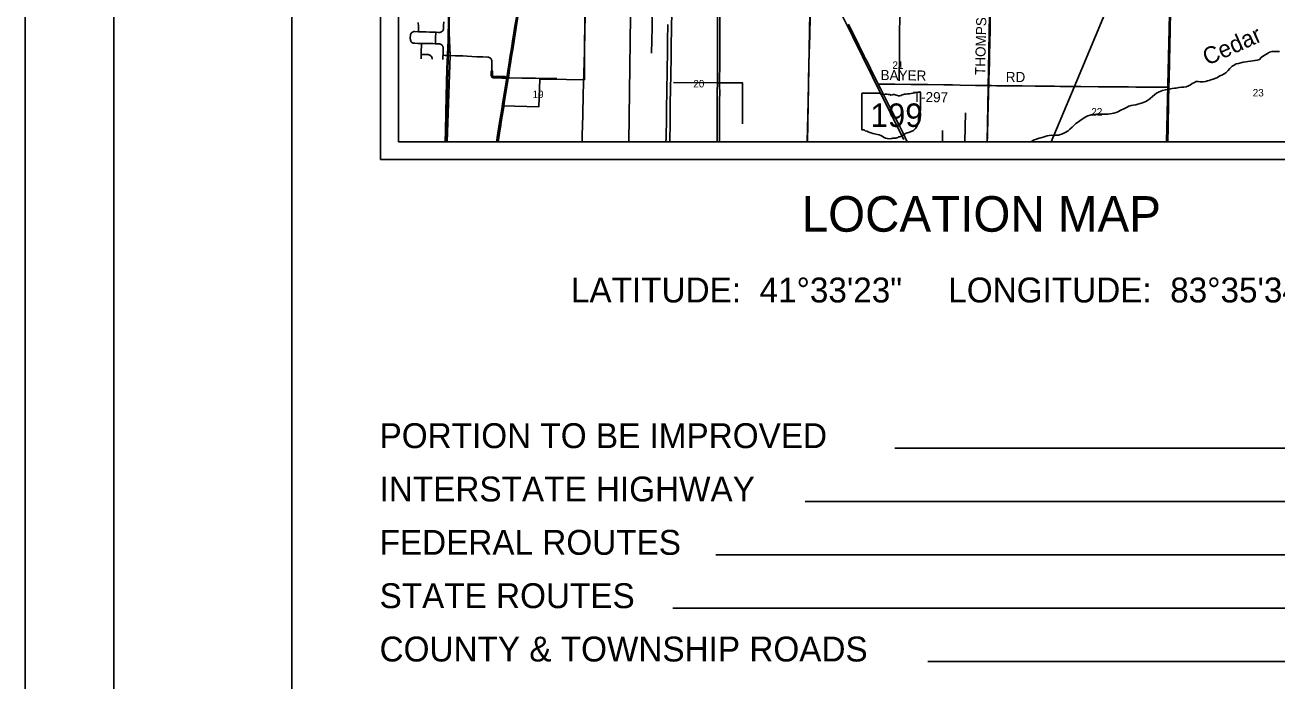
# Model space of a CAD drawing. Extents: x 0 to 34, y 0 to 22.
# Drawn here: x 0 to 7.04, y 11.07 to 14.76 of the extents above; entities that cross this region are included whole.
import ezdxf

# ---------------------------------------------------------------- set-up
doc = ezdxf.new("R2010")
doc.units = 0
for name, color, linetype in [('GM_X_City_Street', 7, 'Continuous'), ('GM_X_Corporation', 7, 'Continuous'), ('GM_X_County_Road', 7, 'Continuous'), ('GM_X_Interstate_Route', 7, 'Continuous'), ('GM_X_Minor_River', 7, 'Continuous'), ('GM_X_Minor_River_Text', 7, 'Continuous'), ('GM_X_Rail_Line', 7, 'Continuous'), ('GM_X_Section_Text', 7, 'Continuous'), ('GM_X_State_Location', 7, 'Continuous'), ('GM_X_State_Route', 7, 'Continuous'), ('GM_X_State_Shield', 7, 'Continuous'), ('GM_X_Township_Road', 7, 'Continuous'), ('GM_X_Township_Road_Text', 7, 'Continuous'), ('SH_Border', 7, 'Continuous'), ('SH_Cut_Line', 7, 'Continuous'), ('SH_Data', 7, 'Continuous'), ('SH_Text', 7, 'Continuous')]:
    doc.layers.add(name, color=color, linetype=linetype)

msp = doc.modelspace()

# ---------------------------------------------------------------- linework, layer by layer
at = {"layer": 'GM_X_City_Street'}
msp.add_line((2.71, 14.4594), (2.7187, 14.4592), dxfattribs=at)
for points in [[(2.3508, 14.5624), (2.3512, 14.5805), (2.3513, 14.586), (2.3513, 14.5954), (2.3519, 14.6215), (2.3519, 14.6284), (2.3515, 14.6316), (2.3509, 14.6341), (2.3499, 14.6366), (2.3482, 14.6394), (2.3463, 14.6419), (2.344, 14.6442), (2.3415, 14.6462), (2.3387, 14.6478), (2.3356, 14.649), (2.3325, 14.6498), (2.3287, 14.6502), (2.3212, 14.6504), (2.3085, 14.6509), (2.3075, 14.6509), (2.2939, 14.6515), (2.2634, 14.6523), (2.2305, 14.6531), (2.2294, 14.6531), (2.2099, 14.6532), (2.1932, 14.6533), (2.1883, 14.6535), (2.1854, 14.6541), (2.1825, 14.655), (2.1793, 14.6566), (2.1768, 14.6582), (2.1745, 14.6602), (2.1725, 14.6624), (2.1709, 14.6649), (2.1695, 14.6675), (2.1683, 14.6709), (2.1676, 14.6745), (2.1673, 14.6781), (2.1673, 14.6861), (2.1677, 14.6972), (2.1681, 14.7008), (2.1689, 14.7037), (2.17, 14.7065), (2.1715, 14.709), (2.1734, 14.7114), (2.1755, 14.7135), (2.1778, 14.7154), (2.1804, 14.7169), (2.1831, 14.7181), (2.186, 14.7189), (2.1889, 14.7194), (2.1926, 14.7196), (2.2131, 14.7187), (2.2192, 14.7185), (2.2571, 14.7171), (2.2758, 14.7165), (2.3103, 14.7153), (2.3124, 14.7152), (2.3255, 14.7146), (2.3318, 14.7145), (2.3343, 14.7147), (2.3369, 14.7153), (2.3399, 14.7164), (2.3428, 14.7179), (2.3449, 14.7193), (2.3474, 14.7215), (2.3495, 14.7239), (2.3513, 14.7266), (2.3527, 14.7295), (2.3538, 14.7325), (2.3544, 14.7357), (2.3548, 14.7401), (2.3548, 14.7532), (2.3551, 14.7749)], [(2.2131, 14.7187), (2.2131, 14.7245), (2.2128, 14.7475), (2.2125, 14.7712)], [(2.2286, 14.5668), (2.2288, 14.573), (2.2291, 14.5908), (2.2293, 14.6046), (2.2294, 14.6442), (2.2294, 14.6531)], [(2.3085, 14.6509), (2.3089, 14.6599), (2.3091, 14.669), (2.3095, 14.6864), (2.3102, 14.7115), (2.3103, 14.7153)], [(2.2291, 14.5908), (2.2316, 14.5907), (2.2364, 14.5906), (2.246, 14.5904), (2.2621, 14.59), (2.2671, 14.5897), (2.2709, 14.5891), (2.274, 14.5883), (2.2769, 14.587), (2.2797, 14.5854), (2.2823, 14.5834), (2.2845, 14.5811), (2.2864, 14.5785), (2.288, 14.5757), (2.2891, 14.5727), (2.2898, 14.5695), (2.29, 14.5663), (2.29, 14.565)], [(2.3513, 14.586), (2.3628, 14.5854), (2.3919, 14.5845), (2.4213, 14.5837), (2.4499, 14.5834), (2.4624, 14.5828), (2.4863, 14.5816), (2.5126, 14.5791), (2.5424, 14.5779), (2.5747, 14.5772), (2.6034, 14.5761), (2.6078, 14.5754), (2.6115, 14.5742), (2.615, 14.5724), (2.618, 14.5699), (2.6206, 14.567), (2.6231, 14.5633), (2.6247, 14.5598), (2.6257, 14.5561), (2.6263, 14.551), (2.6264, 14.541), (2.6258, 14.5105), (2.6256, 14.5014)], [(2.6256, 14.5014), (2.6246, 14.5002), (2.6238, 14.4985), (2.6233, 14.4971), (2.6228, 14.495), (2.6223, 14.4882), (2.6221, 14.4764), (2.6225, 14.472), (2.6233, 14.469), (2.6247, 14.4662), (2.6265, 14.4638), (2.6286, 14.462), (2.6309, 14.4606)], [(2.6256, 14.5014), (2.6266, 14.5005), (2.6275, 14.4995), (2.6279, 14.4986), (2.6283, 14.4976), (2.6288, 14.4958), (2.629, 14.4939), (2.6291, 14.4908), (2.6291, 14.4815), (2.6292, 14.4778), (2.6297, 14.4746), (2.6301, 14.4728), (2.631, 14.4706), (2.6317, 14.4691), (2.6325, 14.4683), (2.6336, 14.4675)], [(2.6309, 14.4606), (2.6324, 14.4599), (2.6349, 14.4591), (2.6376, 14.4588), (2.6417, 14.4588), (2.6813, 14.4581), (2.7013, 14.4579), (2.7046, 14.4581), (2.7078, 14.4586), (2.71, 14.4594)], [(2.6336, 14.4675), (2.6356, 14.4673), (2.6395, 14.467), (2.6688, 14.4667), (2.6981, 14.4662), (2.7002, 14.4659), (2.7024, 14.4653), (2.7042, 14.4647), (2.7063, 14.4633), (2.7084, 14.4615), (2.71, 14.4594)], [(2.7187, 14.4592), (2.7264, 14.459), (2.794, 14.4572), (2.8374, 14.4568), (2.8715, 14.4565), (2.9056, 14.4561), (2.9335, 14.4557), (2.9646, 14.4551), (2.9925, 14.4549)]]:
    msp.add_lwpolyline(points, dxfattribs=at)
at = {"layer": 'GM_X_Corporation'}
for points in [[(2.1, 17.3213), (2.1, 14.1), (8.9, 14.1)], [(2.1, 17.3213), (2.1, 14.1), (2.6563, 14.1), (2.6875, 14.3022), (2.891, 14.2967), (2.8954, 14.4513), (3.0457, 14.4499), (3.1471, 14.4488), (3.1471, 14.4499), (3.1478, 14.4499), (3.149, 14.9551)], [(2.3742, 14.9692), (2.3917, 14.585), (2.3741, 14.1), (8.4543, 14.1)]]:
    msp.add_lwpolyline(points, dxfattribs=at)
for points in [[(2.1, 14.9841), (2.1, 14.1), (2.3664, 14.1), (2.391, 14.9673)], [(2.1, 14.9787), (2.1, 14.1), (2.3741, 14.1), (2.3917, 14.585), (2.3742, 14.9692), (2.3399, 14.9699), (2.3316, 14.9702), (2.3309, 14.9702), (2.3139, 14.9709), (2.2929, 14.9719), (2.2782, 14.9727), (2.2462, 14.9739), (2.1922, 14.9754), (2.1487, 14.9768)], [(2.3664, 14.1), (3.396, 14.1), (3.4087, 14.9463), (2.391, 14.9673)], [(3.396, 14.1), (4.4016, 14.1), (4.4167, 14.9334), (3.4087, 14.9463)], [(4.4016, 14.1), (5.4122, 14.1), (5.428, 14.9189), (4.4167, 14.9334)], [(5.4122, 14.1), (6.4222, 14.1), (6.4397, 14.8975), (5.428, 14.9189)], [(6.4222, 14.1), (7.4432, 14.1), (7.4587, 14.8897), (6.4397, 14.8975)]]:
    msp.add_lwpolyline(points, close=True, dxfattribs=at)
at = {"layer": 'GM_X_County_Road'}
for points in [[(6.4346, 14.409), (6.4348, 14.4157), (6.4358, 14.4449), (6.4367, 14.4847), (6.4375, 14.5158), (6.4381, 14.5406), (6.4384, 14.5624), (6.4389, 14.5823), (6.4394, 14.609), (6.4402, 14.6438), (6.4408, 14.6718), (6.4412, 14.6935), (6.442, 14.7364), (6.4423, 14.7569), (6.4432, 14.8017), (6.4438, 14.8216), (6.4448, 14.8508), (6.4462, 14.9003)], [(6.4285, 14.1), (6.4287, 14.1061), (6.4289, 14.1198), (6.4298, 14.1633), (6.4306, 14.2087), (6.4308, 14.2304), (6.4319, 14.2783), (6.4328, 14.3268), (6.4334, 14.3542), (6.434, 14.3846), (6.4346, 14.409)]]:
    msp.add_lwpolyline(points, dxfattribs=at)
at = {"layer": 'GM_X_Interstate_Route'}
for points in [[(3.6268, 14.1), (3.6269, 14.1057), (3.6285, 14.2052), (3.6297, 14.281), (3.63, 14.2991), (3.6317, 14.4097), (3.6326, 14.4619), (3.6328, 14.4756), (3.633, 14.4918), (3.6342, 14.562), (3.6347, 14.5912), (3.6353, 14.6304), (3.6356, 14.6528), (3.6357, 14.6652), (3.6362, 14.7087), (3.6366, 14.7367), (3.6371, 14.7653), (3.6378, 14.8045), (3.6384, 14.8442), (3.6395, 14.9151), (3.6397, 14.9364)], [(3.6057, 14.1), (3.6061, 14.1202), (3.6067, 14.1463), (3.6077, 14.2084), (3.6081, 14.2345), (3.6083, 14.2501), (3.6088, 14.2849), (3.609, 14.2973), (3.6093, 14.3135), (3.6099, 14.3576), (3.6103, 14.38), (3.6107, 14.4092), (3.6117, 14.477), (3.612, 14.4938), (3.6123, 14.5174), (3.6128, 14.5435), (3.6133, 14.5665), (3.6139, 14.6032), (3.6145, 14.6498), (3.6149, 14.6691), (3.6164, 14.7586)]]:
    msp.add_lwpolyline(points, dxfattribs=at)
at = {"layer": 'GM_X_Minor_River'}
for p, q in [((5.2864, 14.1), (5.2898, 14.2625)), ((5.161, 14.1), (5.1616, 14.1631))]:
    msp.add_line(p, q, dxfattribs=at)
for points in [[(4.9859, 17.7695), (4.9787, 17.5661), (4.97, 17.2993), (4.9652, 17.1654), (4.9566, 16.932), (4.9509, 16.7564), (4.9406, 16.3952), (4.9347, 16.1774), (4.9302, 15.9217), (4.9265, 15.7213), (4.9234, 15.4796), (4.9222, 15.2762), (4.9228, 15.1771), (4.9205, 14.913), (4.9191, 14.6003), (4.9178, 14.4421)], [(4.9429, 14.112), (4.8226, 14.3541), (4.6577, 14.6894), (4.5451, 14.917), (4.403, 15.2019), (4.2999, 15.41), (4.178, 15.6548), (4.0606, 15.8912), (3.9943, 16.0226), (4.0516, 16.097), (4.1146, 16.177), (4.1979, 16.2845), (4.2667, 16.3732), (4.3266, 16.4473), (4.3362, 16.4604), (4.3416, 16.4642), (4.3499, 16.4656), (4.3607, 16.4654)], [(3.8929, 14.1), (3.8942, 14.2215), (3.8933, 14.3828), (3.895, 14.4314), (3.8956, 14.6454), (3.8951, 14.8443), (3.8969, 14.9251), (3.9034, 15.1633), (3.9063, 15.3819), (3.9128, 15.594), (3.9196, 15.8239), (3.9215, 15.913)], [(2.4065, 15.6311), (2.3986, 15.4619), (2.3966, 15.3202), (2.3919, 15.124), (2.388, 14.9783), (2.3866, 14.9548), (2.3825, 14.8011), (2.3801, 14.669), (2.3736, 14.51), (2.3683, 14.3555), (2.3644, 14.1631), (2.3632, 14.1)], [(3.5243, 14.5973), (3.5277, 14.7396), (3.53, 14.8614), (3.5332, 14.9296)], [(4.4003, 14.1), (4.4003, 14.1013), (4.4063, 14.3236), (4.4102, 14.5429), (4.4141, 14.6977), (4.4185, 14.9189)], [(3.1516, 14.8077), (3.1492, 14.7239), (3.1467, 14.6066), (3.1434, 14.4863), (3.1405, 14.3675), (3.1377, 14.2494), (3.1345, 14.1344), (3.1337, 14.1)], [(7.0566, 14.608), (7.0392, 14.6071), (7.0252, 14.6076), (7.015, 14.6081), (7.001, 14.6038), (6.9892, 14.5959), (6.9793, 14.5908), (6.9674, 14.5822), (6.9537, 14.574), (6.9438, 14.5624), (6.932, 14.5591), (6.9188, 14.5562), (6.9063, 14.5552), (6.893, 14.5531), (6.8794, 14.5514), (6.8696, 14.55), (6.8521, 14.5464), (6.8396, 14.5436), (6.8268, 14.5407), (6.8142, 14.5374), (6.8017, 14.5304), (6.7914, 14.5241), (6.7784, 14.5121), (6.7677, 14.4997), (6.755, 14.4877), (6.7455, 14.481), (6.7322, 14.4743), (6.722, 14.4707), (6.7086, 14.4617), (6.698, 14.4573), (6.6847, 14.4522), (6.6707, 14.4478), (6.6612, 14.4445), (6.6513, 14.4423), (6.6399, 14.4387), (6.6278, 14.4369), (6.6105, 14.4375), (6.5999, 14.4388), (6.5882, 14.4378), (6.5752, 14.4308), (6.5654, 14.4267), (6.5555, 14.4204), (6.5456, 14.4148), (6.5326, 14.4078), (6.519, 14.4064), (6.505, 14.4066), (6.4914, 14.4041), (6.4763, 14.4017), (6.4657, 14.401), (6.4536, 14.3993), (6.4441, 14.3967), (6.4293, 14.3939), (6.4153, 14.3922), (6.3994, 14.3886), (6.3895, 14.3849), (6.3759, 14.3786), (6.3656, 14.3727), (6.3549, 14.3649), (6.3419, 14.3533), (6.3293, 14.3439), (6.3194, 14.3357), (6.3057, 14.3256), (6.2962, 14.3223), (6.2859, 14.3183), (6.2726, 14.3143), (6.2609, 14.3106), (6.2491, 14.3077), (6.2329, 14.3049), (6.2226, 14.3031), (6.2094, 14.2991), (6.1995, 14.2951), (6.1808, 14.2851), (6.1645, 14.2765), (6.1478, 14.2688), (6.1379, 14.2647), (6.1254, 14.2611), (6.1152, 14.2593), (6.1053, 14.2576), (6.0913, 14.2555), (6.0781, 14.2549), (6.0633, 14.2547), (6.0505, 14.2548), (6.0403, 14.255), (6.0275, 14.254), (6.0138, 14.2538), (6.004, 14.2524), (5.9915, 14.2491), (5.979, 14.2451), (5.9672, 14.2399), (5.952, 14.2303), (5.9409, 14.2232), (5.9264, 14.2124), (5.9112, 14.2015)], [(3.648, 14.4337), (3.895, 14.4314), (4.0363, 14.4303), (4.0363, 14.1996)], [(5.9112, 14.2015), (5.9016, 14.1926), (5.8905, 14.1821), (5.8783, 14.1708), (5.8676, 14.1615), (5.8516, 14.1511), (5.8371, 14.144), (5.8258, 14.1404), (5.8129, 14.1375), (5.7985, 14.1362), (5.7845, 14.1352), (5.7747, 14.1368), (5.7615, 14.1351), (5.7509, 14.133), (5.7384, 14.1297), (5.7273, 14.1257), (5.7141, 14.122), (5.7042, 14.1191), (5.6891, 14.1148), (5.6765, 14.1096), (5.6647, 14.1025), (5.661, 14.1)]]:
    msp.add_lwpolyline(points, dxfattribs=at)
at = {"layer": 'GM_X_Rail_Line'}
for points in [[(5.7724, 14.1), (5.9023, 14.4065), (6.108, 14.9012), (7.0925, 17.2371), (7.3462, 17.8422), (7.5826, 18.397), (7.8741, 19.1084), (7.9022, 19.1708), (7.9338, 19.2375), (7.9584, 19.2815), (7.9927, 19.3184), (8.0524, 19.3602), (8.3458, 19.5368)], [(2.657, 14.1), (2.9088, 15.6876), (2.96, 16.0522), (2.6402, 16.6697)]]:
    msp.add_lwpolyline(points, dxfattribs=at)
at = {"layer": 'GM_X_State_Route'}
for points in [[(2.71, 14.4594), (2.716, 14.4972), (2.7234, 14.544), (2.728, 14.5729), (2.7361, 14.6249), (2.7447, 14.678), (2.7503, 14.7132), (2.7559, 14.7489), (2.7607, 14.778), (2.7733, 14.8572), (2.7794, 14.8985), (2.7849, 14.9322), (2.789, 14.9586), (2.7891, 14.9594), (2.7893, 14.9604)], [(2.719, 14.4612), (2.7207, 14.4722), (2.7258, 14.506), (2.7314, 14.5404), (2.7375, 14.5797), (2.7454, 14.6295), (2.7573, 14.7056), (2.7708, 14.7904), (2.7817, 14.8598), (2.7822, 14.8627)], [(4.9633, 14.1), (4.9377, 14.1509), (4.9203, 14.1853), (4.8922, 14.2408), (4.8791, 14.2669), (4.8655, 14.2941), (4.8543, 14.3163), (4.8406, 14.3435), (4.8291, 14.3663), (4.8123, 14.3996), (4.8, 14.424), (4.7916, 14.4407), (4.7719, 14.4802), (4.7565, 14.5108), (4.7387, 14.5465), (4.7252, 14.5736), (4.7213, 14.5814), (4.6906, 14.6432), (4.6768, 14.6711), (4.6573, 14.7107), (4.6324, 14.7615)], [(2.6525, 14.1), (2.6539, 14.1089), (2.6585, 14.1364), (2.6639, 14.1715), (2.6736, 14.2305), (2.682, 14.283), (2.6869, 14.3133), (2.6993, 14.3925), (2.7097, 14.4577), (2.71, 14.4594)], [(2.6936, 14.3026), (2.6979, 14.3294), (2.7015, 14.3515), (2.7072, 14.3884), (2.7158, 14.4424), (2.7187, 14.4592), (2.719, 14.4612)], [(2.6608, 14.1), (2.6626, 14.1109), (2.6684, 14.1471), (2.6742, 14.1815), (2.6809, 14.2232), (2.6843, 14.2441), (2.6891, 14.2748), (2.6927, 14.2969), (2.6934, 14.3016), (2.6936, 14.3026)]]:
    msp.add_lwpolyline(points, dxfattribs=at)
at = {"layer": 'GM_X_State_Shield'}
for p, q in [((4.7074, 14.3693), (4.7074, 14.1692)), ((4.8072, 14.3728), (4.7107, 14.3728)), ((5.037, 14.2731), (5.037, 14.3777)), ((5.037, 14.2731), (5.037, 14.2731))]:
    msp.add_line(p, q, dxfattribs=at)
for centre, major_axis, start_param, end_param in [((4.7112, 14.3698), (0.00382, 0), 1.712693, 3.28349), ((4.8302, 14.396), (0.037, 0), 4.042523, 4.731795), ((4.9642, 14.3117), (0.0703, 0), 1.699011, 2.107814), ((4.9196, 14.6456), (0.3495, 0), 4.814394, 5.042369), ((5.0334, 14.3782), (0.00367, 0), 6.141152, 7.989035), ((4.8425, 14.2604), (0.133, 0), 1.404758, 1.657858), ((4.8726, 14.3708), (0.0107, 0), 3.836095, 5.185415), ((4.8883, 14.3477), (0.0222, 0), 0.950623, 2.079405), ((4.917, 14.3794), (0.0267, 0), 4.081561, 5.145723), ((4.9392, 14.2159), (0.0874, 0), 5.101752, 6.440018), ((5.0502, 14.2292), (0.0248, 0), 2.387724, 3.262537), ((5.0362, 14.2654), (0.00568, 0), 1.883978, 3.671073), ((5, 14.2521), (0.0341, 0), 5.934695, 6.695948), ((5.0331, 14.2726), (0.00393, 0), 5.05454, 6.418171), ((4.7112, 14.1688), (0.00385, 0), 3.00124, 4.508301), ((4.7118, 14.1893), (0.0294, 0), 4.665946, 4.897461), ((4.7178, 14.1577), (0.0106, 0), 0.519207, 1.627899), ((4.8517, 14.3375), (0.2524, 0), 4.195997, 4.488961), ((4.7764, 14.0793), (0.079, 0), 0.823519, 1.323587), ((4.8618, 14.1567), (0.0501, 0), 4.026481, 4.996735), ((4.8908, 14.0875), (0.0412, 0), 1.495662, 1.94098), ((4.8944, 14.1417), (0.0267, 0), 4.691044, 5.507374), ((4.9186, 14.1223), (0.00752, 0), 1.147584, 2.315152), ((4.9154, 14.1498), (0.0282, 0), 4.937069, 5.64225), ((4.9761, 14.113), (0.0479, 0), 1.647645, 2.488434)]:
    msp.add_ellipse(centre, major_axis=major_axis, ratio=0.8, start_param=start_param, end_param=end_param, dxfattribs=at)
at = {"layer": 'GM_X_Township_Road'}
for points in [[(3.907, 14.1), (3.9071, 14.1253), (3.9072, 14.1577), (3.9071, 14.1925), (3.9072, 14.2124), (3.9074, 14.2783), (3.9075, 14.3125), (3.9076, 14.3417), (3.9077, 14.3691), (3.9074, 14.4195), (3.9076, 14.4605), (3.9078, 14.5171), (3.9079, 14.5432), (3.9079, 14.5662), (3.9079, 14.6284), (3.908, 14.6508), (3.9081, 14.7012), (3.9084, 14.7577), (3.9084, 14.7963), (3.9084, 14.8492), (3.9086, 14.8952), (3.9086, 14.9151), (3.9085, 14.9393), (3.9086, 14.9432)], [(5.4213, 14.4156), (5.4215, 14.4215), (5.4222, 14.45), (5.4236, 14.4992), (5.4253, 14.5456), (5.4255, 14.5657), (5.4257, 14.5877), (5.4262, 14.6113), (5.4271, 14.6349), (5.4277, 14.6504), (5.4282, 14.6696), (5.4292, 14.7175), (5.4293, 14.7363), (5.4294, 14.7506), (5.4295, 14.7766), (5.4298, 14.7902), (5.4301, 14.8052), (5.4306, 14.8313), (5.431, 14.8443), (5.4315, 14.8611), (5.4325, 14.8916), (5.4332, 14.9093), (5.4337, 14.9202)], [(4.8, 14.424), (4.8073, 14.424), (4.84, 14.4238), (4.8758, 14.4236), (4.8939, 14.4233), (4.9856, 14.4224), (5.0406, 14.4215), (5.0791, 14.4208), (5.169, 14.4198), (5.2167, 14.4192), (5.2605, 14.4185), (5.3467, 14.417), (5.4213, 14.4156)], [(5.4127, 14.1), (5.4135, 14.1271), (5.4143, 14.1596), (5.4156, 14.2102), (5.4167, 14.2508), (5.4174, 14.2856), (5.4182, 14.3159), (5.4192, 14.3512), (5.4201, 14.3852), (5.4213, 14.4156)], [(5.4213, 14.4156), (5.4362, 14.4154), (5.4648, 14.4149), (5.5046, 14.4144), (5.5419, 14.4139), (5.6097, 14.4134), (5.6818, 14.4128), (5.7472, 14.412), (5.7912, 14.4116), (5.8241, 14.4112), (5.8919, 14.4104), (5.9049, 14.4104), (5.9399, 14.4101), (6.0392, 14.4094), (6.1138, 14.409), (6.1766, 14.4083), (6.2083, 14.4081), (6.2482, 14.4076), (6.3146, 14.4075), (6.3563, 14.4072), (6.3923, 14.4069), (6.4103, 14.407), (6.4179, 14.4072), (6.4215, 14.4073), (6.4243, 14.4076), (6.4303, 14.4084), (6.4346, 14.409)]]:
    msp.add_lwpolyline(points, dxfattribs=at)
at = {"layer": 'SH_Border'}
for points in [[(0.5, 21.5), (1.5, 21.5), (1.5, 0.5), (0.5, 0.5)], [(1.5, 21.5), (33.5, 21.5), (33.5, 0.5), (1.5, 0.5)]]:
    msp.add_lwpolyline(points, close=True, dxfattribs=at)
at = {"layer": 'SH_Cut_Line'}
msp.add_lwpolyline([(0, 0), (34, 0), (34, 22), (0, 22)], close=True, dxfattribs=at)
at = {"layer": 'SH_Data'}
for p, q in [((2, 21), (2, 14)), ((2, 21), (2, 14)), ((2.1, 20.9), (2.1, 14.1)), ((2.1, 20.9), (2.1, 14.1)), ((2.1, 14.1), (8.9, 14.1)), ((2.1, 14.1), (2.1, 14.1)), ((2.1, 14.1), (8.9, 14.1)), ((2, 14), (9, 14)), ((2, 14), (9, 14)), ((7.7, 12.3767), (4.8937, 12.3767)), ((7.7, 12.0767), (4.3895, 12.0767)), ((7.7, 11.7767), (3.8854, 11.7767)), ((7.7, 11.4767), (3.6448, 11.4767)), ((7.7, 11.1767), (5.0782, 11.1767))]:
    msp.add_line(p, q, dxfattribs=at)

# ---------------------------------------------------------------- texts
at = {"layer": 'GM_X_Minor_River_Text'}
msp.add_text('Cedar', height=0.09476, rotation=24.194, dxfattribs=at).set_placement((6.651, 14.5266))
at = {"layer": 'GM_X_Section_Text'}
for s, p in [('21', (4.8796, 14.5098)), ('20', (3.7592, 14.4053)), ('19', (2.855, 14.3453)), ('23', (6.9062, 14.3545)), ('22', (5.9983, 14.2473))]:
    msp.add_text(s, height=0.04186, rotation=0.00001, dxfattribs=at).set_placement(p)
at = {"layer": 'GM_X_State_Location'}
msp.add_text('199', height=0.000189, rotation=0.00001, dxfattribs=at).set_placement((4.8017, 14.2422))
for s in ['s', 'r']:
    msp.add_text(s, height=0.000189, dxfattribs=at).set_placement((4.8685, 14.256))
at = {"layer": 'GM_X_State_Shield'}
msp.add_text('199', height=0.13184, dxfattribs=at).set_placement((4.7559, 14.1833))
at = {"layer": 'GM_X_Township_Road_Text'}
for s, rotation, p in [('THOMPSON', 88.76892, (5.401, 14.4748)), ('BAYER', 359.19455, (4.8124, 14.4469)), ('RD', 359.51817, (5.5169, 14.436)), ('T-297', 359.15796, (4.9939, 14.3241))]:
    msp.add_text(s, height=0.05682, rotation=rotation, dxfattribs=at).set_placement(p)
at = {"layer": 'SH_Text'}
for s, height, p in [('LOCATION MAP', 0.2, (4.3691, 13.5938)), ('LATITUDE:  41°33\'23"     LONGITUDE:  83°35\'34"', 0.14, (3.071, 13.1959)), ('PORTION TO BE IMPROVED', 0.14, (1.9944, 12.3767)), ('INTERSTATE HIGHWAY', 0.14, (1.9944, 12.0767)), ('FEDERAL ROUTES', 0.14, (1.9944, 11.7767)), ('STATE ROUTES', 0.14, (1.9944, 11.4767)), ('COUNTY & TOWNSHIP ROADS', 0.14, (1.9944, 11.1767))]:
    msp.add_text(s, height=height, dxfattribs=at).set_placement(p)

doc.saveas('drawing.dxf')
